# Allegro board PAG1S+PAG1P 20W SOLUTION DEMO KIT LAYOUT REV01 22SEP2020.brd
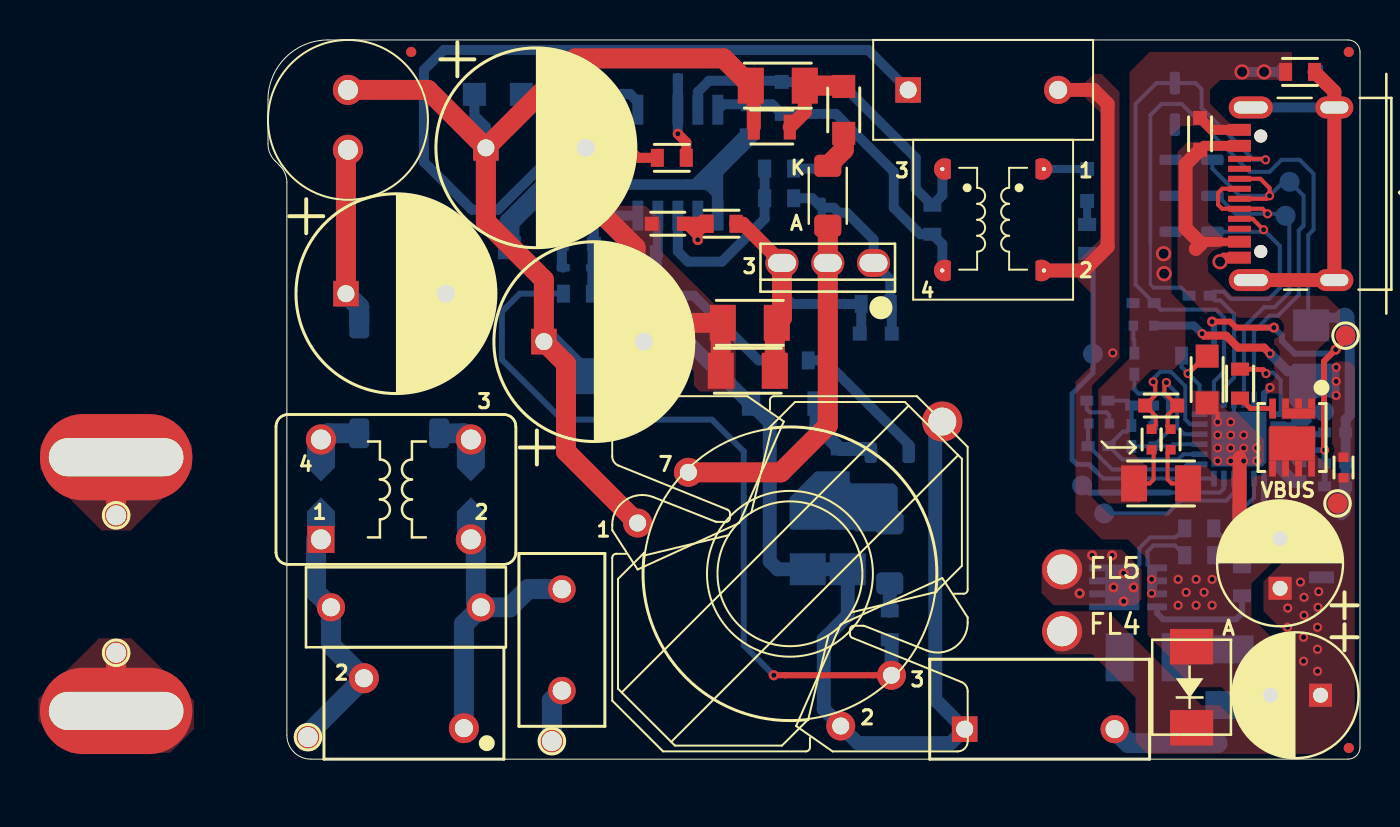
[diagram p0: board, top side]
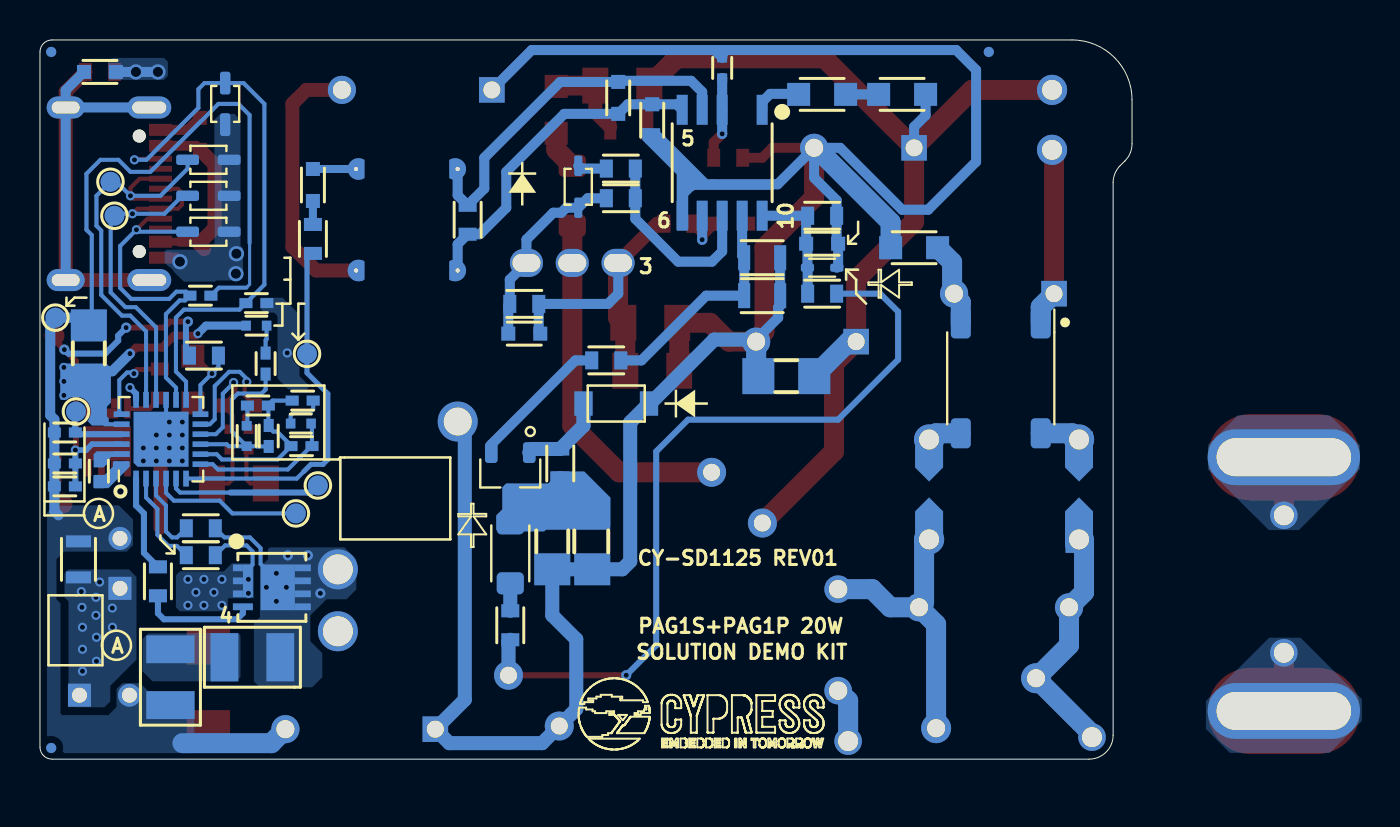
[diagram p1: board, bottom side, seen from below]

Outline 54.62 x 36 mm; copper layers: TOP, BOTTOM. Coordinates in mm from the lower left corner of the outline.
Outline path: 0,33 arc(0.88,35.12) 3,36 54.02,36 arc(54.45,35.82) 54.62,35.4 54.62,0.6 arc(54.45,0.18) 54.02,0 2.14,0 arc(1.3,0.35) 0.94,1.2 0.94,28.86 arc(0.85,29.32) 0.59,29.71 0.35,29.95 arc(0.09,30.34) 0,30.8 0,33

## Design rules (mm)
constraint set DEFAULT: min track width 0.152
net group 400V: nets N14642513 N14642535 VDC_IN
net group AC: nets L N N14611440 N14642330 N14642346
net group FET_DRAIN: nets N14787638 N14814894 N148149671
net group PRIMARY SIDE: nets N14785175 N14787619 N14791099 N14871077

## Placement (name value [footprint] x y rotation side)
ACC7  5200  [PCBBLADE]  -7.6 2.41 90 bottom
ACC8  5200  [PCBBLADE]  -7.6 15.11 90 bottom
BD1  ABS210-13  [SOPA4P400_505X640X170L100X60]  6.56 19.06 180 bottom
C1  10uF  [CAPPRD600W60D1000H2150]  6.4 23.3 0 top
C2  10uF  [CAPPRD600W60D1000H2150]  13.4 30.6 0 top
C3  10uF  [CAPPRD600W60D1000H2150]  16.3 20.9 0 top
C4  100pF  [CAPC1608X90N_TY]  30.4 21.3 180 bottom
C5  1nF  [CAPC2012X70N_MURATA]  25.2 31.64 0 top
C7  2.2nF  [1210]  44 5.1 0 bottom
C8  470uF  [CAPPRD250W50D630H1400]  50.62 9.8 90 top
C9  470uF  [CAPPRD250W50D630H1400]  51.4 3.2 180 top
C10  0.1uF  [CAPC1005X56N_CYPS]  51.68 14.41 270 bottom
C11  0.1uF  [CAPC1005X56N_CYPS]  53.38 13.65 0 bottom
C12  4.7uF  [CAPC1005X56N_CYPS]  53.38 14.8 0 bottom
C13  1uF  [CAPC1005X56N_CYPS]  53.38 16.35 0 bottom
C14  390pF  [CAPC1005X56N_CYPS]  46.6 23.2 180 bottom
C15  390pF  [CAPC1005X56N_CYPS]  43.8 22.83 180 bottom
C16  22nF  [SMD_1206]  17.29 19.17 0 bottom
C17  0.1uF  [CAPC1608X90N_TY]  24 31.98 270 bottom
C20  2.2uF  [SMD_1206]  29 10.9 270 bottom
C21  2.2uF  [SMD_1206]  27 10.9 270 bottom
C23  0.1uF  [CAPC1608X90N_TY]  44.68 17.7 180 top
C24  2.2uF  [CAPC1608X90N_TY]  46.62 31.3 90 top
C25  47nF  [CAPC1005X56N_CYPS]  41.48 17.95 0 bottom
C26  100pF  [CAPC1005X56N_CYPS]  41.54 15.67 0 bottom
C27  10pF  [CAPC1005X56N_CYPS]  43.18 16.18 90 bottom
C28  1nF  [CAPC1005X56N_CYPS]  43.72 17.7 180 bottom
C29  2.2nF  [CAPC1005X56N_CYPS]  43.34 19.8 270 bottom
C31  220pF  [CAPC1608X90N_TY]  20 26.8 180 top
C33  10pF  [CAPC1608X90N_TY]  15.5 25.8 180 bottom
C35  22uF  [CAPC2012X70N_MURATA]  18.5 25.1 180 bottom
C36  3.3nF  [CAPC1608X90N_TY]  40.97 28.74 270 bottom
C38  10uF  [SMD_1206]  52.18 20.31 90 bottom
C39  2200pF  [CAPC1608X90N_TY]  51.62 34.4 0 bottom
C40  10uF  [CAPC2012X70N_MURATA]  52.7 10 90 bottom
C41  22uF  [CAPC2012X70N_MURATA]  18.5 23.2 180 bottom
C42  10pF  [CAPC1608X90N_TY]  25.7 33.1 270 bottom
CX1  33nF, 310VAC  [BFC233820333]  6.9 7.6 180 top
CY1  220pF  [CAPRB750W60L1400T500H1600]  35.77 33.5 0 top
CY2  220pF  [CAPRB750W60L1400T500H1600]  38.6 1.5 0 top
D1  CGRKM4007-HF  [SODFL350X180X115L60X107N]  28 28.2 270 top
D3  RS1MSWF-7  [SODFL350X180X115L60X107N]  31.1 10.3 270 bottom
D5  BZT52C16-TP  [BZT52C12-TP_SOD123]  25.8 17.8 0 bottom
D7  1N4148WS  [SODFL250X125X90L60X30N]  27.7 28.65 270 bottom
D10  BAT54XV2T1G  [BAT54XV2T1G_SOD523]  15.5 24.6 180 bottom
D12  SMBJ5352B-TP  [DO214AA_MICRO]  46.2 3.6 270 top
D13  DESD5V0S1BA-7  [SOD250X130X110L30X30N]  46.2 26.4 180 bottom
D14  DESD5V0S1BA-7  [SOD250X130X110L30X30N]  45.36 32.8 270 bottom
D15  DESD5V0S1BA-7  [SOD250X130X110L30X30N]  46.2 28.2 180 bottom
D16  DESD5V0S1BA-7  [SOD250X130X110L30X30N]  46.2 30 180 bottom
DM  TEST_POINT  [TP-43R_S]  50.9 27.2 270 bottom
DP  TEST_POINT  [TP-43R_S]  51.1 28.9 90 bottom
F1  RSTA 2 AMMO  [FUSRR508W62L885T450H790]  14.7 5.97 270 top
GPIO0  TEST_POINT  [TP-43R_S]  40.72 13.7 90 bottom
GPIO1  TEST_POINT  [TP-43R_S]  41.27 20.29 180 bottom
J1  CU1816SAH1MD2R0-LF-HC  [USB-PD_TYPE-C]  55.94 28.3 90 top
L  TEST_POINT  [TP-43R_S]  14.2 0.9 0 top
L1  100uH, 0.5A  [INDRD300W60D800H10001]  4 32 90 top
L2  600ohm@100Mhz  [RESC2012X70N_PEC]  10.9 25.6 0 bottom
L_  TEST_POINT  [TP-43R_S]  -7.6 5.32 270 top
LF1  300uH, 1A  [L3]  6.4 13.5 0 top
N  TEST_POINT  [TP-43R_S]  2 1.1 0 top
N_  TEST_POINT  [TP-43R_S]  -7.6 12.2 270 top
NOREF  -  []  0.94 1.2 0 top
NOREF#2  -  []  0.08 30.36 0 top
NOREF#3  -  []  26.58 23.4 0 top
NOREF#4  -  []  -10.95 2.62 0 top
NOREF#5  -  []  -10.76 13.97 0 top
NOREF#6  -  [unnamed#2]  54.06 0.56 0 top
NOREF#7  -  []  -13.3 -0.84 0 top
NOREF#8  -  []  20.58 11.97 0 top
NOREF#9  -  []  123.79 -108.26 0 top
NOREF#10  -  []  36.82 30.44 0 top
NOREF#11  -  []  -13.6 17.78 0 top
NOREF#12  -  [unnamed#2]  54.06 35.4 0 top
NOREF#13  -  []  28.02 44.2 0 top
NOREF#14  -  []  40.6 5.64 0 top
NOREF#15  -  []  0 33 0 top
NOREF#16  -  []  54.46 0.19 0 top
NOREF#17  -  []  39.06 22.06 0 top
NOREF#18  -  []  123.79 -108.26 0 top
NOREF#19  -  []  1.62 35.66 0 top
NOREF#20  -  []  -12.85 -1 90 top
NOREF#21  -  [unnamed#2]  7.16 35.4 0 top
NOREF#22  -  []  38.6 8.7 0 top
NOREF#23  -  []  54.02 0 90 top
NOREF#24  -  [unnamed#2]  7.16 35.4 180 bottom
NOREF#25  -  [unnamed#2]  54.06 35.4 180 bottom
NOREF#26  -  [unnamed#2]  54.06 0.56 180 bottom
Q1  IPS70R900P7SAKMA1  [TO229P230X654X875-3B]  28 24.84 180 top
Q2  MMBTA06LT1G  [SOT23-3P95_240X100L40X44N]  31.1 14.3 0 bottom
Q3  BSZ097N10NS5ATMA1  [TSDSON65P330X330X110-8N_A]  43.02 8.6 180 bottom
Q4  BSZ0902NSATMA1  [TSDSON65P330X330X110-8N_A]  51.22 16.1 270 top
R1  820mohm  [RESC3216X65N_ROHM]  24 19.44 180 top
R2  47K  [RESC1608X55N_PEC]  30.4 22.79 0 bottom
R3  402K  [RESC3216X65N_ROHM]  25.5 33.72 0 top
R4  820mohm  [RESC3216X65N_ROHM]  24.1 21.84 180 top
R7  10E  [1210]  48.1 4.1 90 bottom
R8  5m  [RESC3216X65N_ROHM]  44.67 13.8 0 top
R11  100K  [RESC1608X55N_PEC]  46.42 20.2 0 bottom
R16  30E  [RESC1608X55N_PEC]  25.57 28.08 0 bottom
R17  3K  [RESC1608X55N_PEC]  33.23 27 270 bottom
R18  11E  [RESC1608X55N_PEC]  31.1 6.7 270 bottom
R19  1K  [RESC1608X55N_PEC]  22.68 26.8 0 top
R20  200K  [RESC1608X55N_PEC]  28.6 14.8 90 bottom
R21  49.9E  [RESC1608X55N_PEC]  40.97 26.04 90 bottom
R22  4.99K  [RESC1608X55N_PEC]  46.58 11.56 180 bottom
R23  0E  [RESC1005X40N_PEC]  45.15 16 270 top
R24  0E  [RESC1005X40N_PEC]  44.2 16 270 top
R25  2.2E  [RESC1608X55N_PEC]  48.72 8.9 270 bottom
R26  2.2E  [RESC1608X55N_PEC]  48.62 18.8 270 top
R27  40.2K  [RESC1005X40N_PEC]  41.57 16.8 180 bottom
R28  1.2M  [RESC1005X40N_PEC]  44.28 16.18 270 bottom
R29  1K  [RESC1005X40N_PEC]  43.8 21.7 0 bottom
R32  0E  [RESC1608X55N_PEC]  46.58 10.21 180 bottom
R36  499K  [RESC1608X55N_PEC]  20.2 30.1 0 top
R37  47 OHM  [RESC2012X70N_PEC]  15.5 33.27 180 bottom
R40  4.53K  [RESC1608X55N_PEC]  15.5 27.2 0 bottom
R41  0E  [RESC1608X55N_PEC]  51.62 34.4 180 top
R42  261K  [RESC1608X55N_PEC]  15.5 23.3 180 bottom
R43  47 OHM  [RESC2012X70N_PEC]  11.5 33.27 180 bottom
R44  100E  [RESC2012X70N_PEC]  28.8 32.5 90 top
R45  2.2E  [RESC1608X55N_PEC]  25.57 29.56 0 bottom
R48  0E  [RESC1608X55N_PEC]  26.3 19.96 0 bottom
R49  0E  [RESC1005X40N_PEC]  53.8 14.6 270 top
R50  499K  [RESC1005X40N_PEC]  20.5 34.6 270 bottom
RT1  100K  [RESC2012X70N_PEC]  46.98 19 90 top
SGND  TEST_POINT  [TP-43R_S]  53.85 22.1 90 bottom
T1  -  [RM7]  26.11 9.28 0 top
T2  1:3  [RADIAL_R113426000]  36.27 27 180 top
U1  PAG1S  [QFN50P400X400X60-25T275X275N]  48.57 16.01 90 bottom
U2  PAG1P  [SOIC100P600X175-10N_CYPS]  20.5 29.85 270 bottom
VBUS_IN  TEST_POINT  [TP-43R_S]  53.5 12.8 90 top
VCCD  TEST_POINT  [TP-43R_S]  52.82 17.4 180 bottom
VDDD  TEST_POINT  [TP-43R_S]  53.9 21.2 0 top
VR1  V320LA7P  [VAR_V320LA7P]  7.3 2.8 180 top
XRES  TEST_POINT  [TP-43R_S]  41.82 12.3 270 bottom

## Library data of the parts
ACC7 ACC8 = HEYCO PCB BLADE 5201_0
BD1 = BR805D_1
C1-C3 C8 C9 = CAP_2
C4 C5 C7 C10-C17 C20 C21 C23-C29 C31 C33 C35 C36 C38-C42 CX1 CY1 CY2 = 0_0.01uF-50V-10%-X7R-0603
D1 D7 = DIODE_13
D3 = DIODE_17
D5 D12 = DIODE SCHOTTKY_19
D10 = DIODE SCHOTTKY_21
D13-D16 = TVS DIODE_1
DM DP GPIO0 GPIO1 L L_ N N_ SGND VBUS_IN VCCD VDDD XRES = TEST_POINT
F1 = Fuse 2
J1 = USB-PD_TYPE-C_7
L1 L2 = INDUCTOR_PAG1S_1
LF1 = INDUCTOR IRON_8
Q1 = IPP65R380E6XKSA1_1
Q2 = 2N1070_1
Q3 Q4 = DMTH10H010LCT_5
R1-R4 R7 R8 R18 R20 = RESISTOR
R11 R16 R17 R19 R21-R29 R32 R36 R37 R40-R45 R48-R50 = 330 ohm 5% 0805_0
RT1 = RESISTOR VAR 2_4
T1 = PA5222NL_35
T2 = TRANSFORMER_11
U1 = PAG1S_11
U2 = PAG1P_3
VR1 = RESISTOR VAR 2_0

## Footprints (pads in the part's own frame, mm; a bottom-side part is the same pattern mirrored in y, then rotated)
1210
  rect 1.397x2.413 smd: 1(-1.397,0) 2(1.397,0)
BAT54XV2T1G_SOD523
  custom 0.1x0.1 smd: A(0.735,0) C(-0.735,0)
BFC233820333
  round 1.412 hole 0.904: 1(-3.75,0) 2(3.75,0)
BZT52C12-TP_SOD123
  rect 0.914x1.219 smd: A(-1.638,0) K(1.638,0)
CAPC1005X56N_CYPS
  rect 0.65x0.5 smd: 1(-0.525,0) 2(0.525,0)
CAPC1608X90N_TY
  rect 0.7x0.7 smd: 1(-0.8,0) 2(0.8,0)
CAPC2012X70N_MURATA
  rect 0.6x1.25 smd: 1(-0.9,0) 2(0.9,0)
CAPPRD250W50D630H1400
  rect 1.15x1.15 hole 0.75: 1(-1.25,0)
  round 1.15 hole 0.75: 2(1.25,0)
CAPPRD600W60D1000H2150
  rect 1.28x1.28 hole 0.85: 1(-2.5,0)
  round 1.412 hole 0.904: 2(2.5,0)
CAPRB750W60L1400T500H1600
  rect 1.28x1.28 hole 0.85: 1(-3.75,0)
  round 1.412 hole 0.904: 2(3.75,0)
DO214AA_MICRO
  rect 1.778x2.159 smd: A(-2.032,0) K(2.032,0)
FUSRR508W62L885T450H790
  round 1.38 hole 0.92: 1(-2.54,0) 2(2.54,0)
INDRD300W60D800H10001
  round 1.508 hole 1: 1(-1.5,0) 2(1.5,0)
L3
  rect 1.35x1.35 hole 1: 1(-3.75,-2.5)
  round 1.508 hole 1: 2(3.75,-2.5) 3(3.75,2.5) 4(-3.75,2.5)
PCBBLADE
  oval 4.318x7.62 hole 1.905x6.731: 1(0,0)
QFN50P400X400X60-25T275X275N
  rect 0.79x0.28 smd: 1(-1.97,1.25) 2(-1.97,0.75) 3(-1.97,0.25) 4(-1.97,-0.25) 5(-1.97,-0.75) 6(-1.97,-1.25) 13(1.97,-1.25) 14(1.97,-0.75) 15(1.97,-0.25) 16(1.97,0.25) 17(1.97,0.75) 18(1.97,1.25)
  rect 0.28x0.79 smd: 7(-1.25,-1.97) 8(-0.75,-1.97) 9(-0.25,-1.97) 10(0.25,-1.97) 11(0.75,-1.97) 12(1.25,-1.97) 19(1.25,1.97) 20(0.75,1.97) 21(0.25,1.97) 22(-0.25,1.97) 23(-0.75,1.97) 24(-1.25,1.97)
  custom 0.687x0.687 smd: 25(0,0)
RADIAL_R113426000
  custom 0.21x0.21 hole 0.7: 1(-2.54,-2.54) 2(-2.54,2.54) 3(2.54,-2.54) 4(2.54,2.54)
RESC1005X40N_PEC
  rect 0.475x0.5 smd: 1(-0.512,0) 2(0.512,0)
RESC1608X55N_PEC
  rect 0.65x0.9 smd: 1(-0.725,0) 2(0.725,0)
RESC2012X70N_PEC
  rect 1.15x1.15 smd: 1(-1.175,0) 2(1.175,0)
RESC3216X65N_ROHM
  rect 1.3x1.8 smd: 1(-1.35,0) 2(1.35,0)
RM7
  round 1.45 hole 0.85: 1(-7.62,2.54) 2(2.54,-7.62) 3(5.08,-5.08) 7(-5.08,5.08)
  round 2 hole 1.5: 9(13.615,0.222) 10(13.615,-2.878)
  round 2 hole 1.4: 11(7.62,7.62)
SMD_1206
  rect 1.6x1.803 smd: 1(-1.397,0) 2(1.397,0)
SOD250X130X110L30X30N
  custom 0.13x0.13 smd: A(1.04,0) C(-1.04,0)
SODFL250X125X90L60X30N
  custom 0.1x0.1 smd: A(1.05,0) C(-1.05,0)
SODFL350X180X115L60X107N
  custom 0.278x0.278 smd: A(1.5,0) C(-1.5,0)
SOIC100P600X175-10N_CYPS
  rect 1.5x0.55 smd: 1(-2.65,2) 3(-2.65,0) 4(-2.65,-1) 5(-2.65,-2) 6(2.65,-2) 7(2.65,-1) 8(2.65,0) 9(2.65,1) 10(2.65,2)
SOPA4P400_505X640X170L100X60
  custom 0.25x0.25 smd: 1(2,2.75) 2(2,-2.75) 3(-2,2.75) 4(-2,-2.75)
SOT23-3P95_240X100L40X44N
  custom 0.158x0.158 smd: 1(-0.95,-1.045) 2(0.95,-1.045) 3(0,1.045)
TO229P230X654X875-3B
  oval 1.654x1.408 hole 1.4x0.9: 1(-2.29,0) 2(0,0) 3(2.29,0)
TP-43R_S
  round 1.38 hole 1: 1(0,0)
TSDSON65P330X330X110-8N_A
  rect 0.5x0.34 smd: 1(-1.7,0.975) 2(-1.7,0.325) 3(-1.7,-0.325)
  rect 1x0.34 smd: 4(-1.45,-0.975)
  rect 0.8x0.34 smd: 5(1.55,-0.975) 6(1.55,-0.325) 7(1.55,0.325) 8(1.55,0.975)
unnamed#2
  round 0.508 smd: (0,0)
USB-PD_TYPE-C
  round 0.65 hole 0.65 unplated: (-2.89,6.28) (2.89,6.28)
  rect 0.6x1.15 smd: A1(-3.2,7.345) A4(-2.4,7.345) B1(3.2,7.345) B4(2.4,7.345)
  rect 0.3x1.15 smd: A5(-1.25,7.345) A6(-0.25,7.345) A7(0.25,7.345) A8(1.25,7.345) A9(2.4,7.345) A12(3.2,7.345) B5(1.75,7.345) B6(0.75,7.345) B7(-0.75,7.345) B8(-1.75,7.345) B9(-2.4,7.345) B12(-3.2,7.345)
  oval 1.1x1.9 hole 0.6x1.4: MH1(-4.32,2.6) MH2(4.32,2.6)
  oval 1.1x2.2 hole 0.6x1.7: MH3(4.32,6.78) MH4(-4.32,6.78)
VAR_V320LA7P
  round 1.5 hole 0.904: 1(-2.5,1.25) 2(2.5,-1.25)

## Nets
VBUS_C: C24.1 J1.A4 J1.A9 J1.B4 J1.B9(VBUS_4) Q4.1 Q4.2 Q4.3(S#3) U1.18
VBUS_IN: C8.1 C9.1 C40.1 D12.K Q4.5 Q4.6 Q4.7 Q4.8 R49.2 T1.10 VBUS_IN.1
VCCD: C13.1 U1.21 VCCD.1
VDDD: C11.1 C12.1 R11.2 U1.22 VDDD.1
CC1: C14.1 D13.C J1.A5 U1.14
CC2: C15.1 D14.C J1.B5 U1.13
DM_GPIO4: D15.C DM.1 J1.A7 J1.B7 U1.16
DP_GPIO5: D16.C DP.1 J1.A6 J1.B6 U1.17
L: F1.2 L.1
L_: ACC7.1 L_.1
N: CX1.2 LF1.1 N.1 VR1.2
N_: ACC8.1 N_.1
PE_GND: C2.2 C3.2 C16.2 C17.2 C20.2 C21.2 C31.2 C33.2 C35.2 C41.2 CY1.1 CY2.1 D5.A D10.A L2.2 R1.2 R4.2 R36.1 R40.1 R50.1 T1.2 T1.11 U2.6
PWM_DRV_GPIO1: GPIO1.1 R21.1 U1.6
SE_GND: C8.2 C9.2 C11.2 C12.2 C13.2 C14.2 C15.2 C38.2 C40.2 CY1.2 CY2.2 D12.A Q3.1 Q3.2 Q3.3(S#3) R7.1 R8.2 R23.2 R32.2 RT1.1 SGND.1 T2.2 U1.15 U1.25
SR_GDRV: R25.1 U1.1
SR_SENSE: R22.1 U1.3
TYPE-C_GND: C24.2 C39.1 D13.A D14.A D15.A D16.A J1.A1 J1.A12 J1.B1 J1.B12 R8.1 R24.2 R41.2
VDC_IN: C2.1 C3.1 C5.1 C16.1 L1.2 R3.1 R43.2 T1.1
N14611440: CX1.1 F1.1 LF1.2 VR1.1
N14642330: BD1.4 LF1.3
N14642346: BD1.2 LF1.4
N14642513: BD1.1(DC OUT PLUS) C1.1 L1.1
N14642535: BD1.3 C1.2 L2.1
N14649078: C7.1 Q3.5 Q3.6 Q3.7 Q3.8 R22.2 T1.9(OUT3)
N14679612: Q4.4 R26.2
N14684319: R11.1 RT1.2 U1.12
N14693071: C23.1 R23.1 U1.10
N14693222: C23.2 R24.1 U1.11
N14693774: GPIO0.1 U1.5
N14694144: C25.2 C26.2 C27.2 C28.2 U1.8
N14694182: C26.1 R27.2 U1.7
N14694200: C27.1 C29.2 R28.2 U1.9
N14702573: C38.1 R29.2 R49.1 U1.20
N14702669: C10.2 U1.24
N14702673: C10.1 U1.23
N14714455: U1.4(XRES) XRES.1
N14737770: R32.1 U1.2
N14785175: D5.K Q2.1 R20.2
N14785189: C20.1 C21.1 D3.C Q2.3 R20.1
N14787619: Q2.2(E) R48.2
N14787638: D1.A Q1.2 T1.7
N14791099: C35.1 C41.1 R48.1 U2.9
N14814894: C5.2 R3.2 R44.2
N14820915: C39.2 J1.MH1 J1.MH2 J1.MH3 J1.MH4 R41.1
N14862097: C4.1 D7.A Q1.1 R2.2 R16.2
N14862239: R16.1 R45.1 U2.8
N14862483: C17.1 C42.2 R17.2 T2.4 U2.5
N14862590: C42.1 R17.1 T2.3 U2.4
N14862769: C31.1 R19.1 U2.7
N14862985: R37.1 U2.1(VDD700)
N14865019: C33.1 D10.C(K) R40.2 R42.1 U2.10
N14871077: C4.2 Q1.3(S) R1.1 R2.1 R4.1 R19.2
N14908282: R36.2 R50.2 U2.3
N14923159: R37.2 R43.1
N14933197: R26.1 U1.19
N14933813: D3.A R18.1
N14956400: D7.C R45.2
N14974360: C36.2 R21.2
N14974376: C36.1 T2.1
N14975051: C28.1 R28.1
N14975285: C25.1 R27.1
N14978138: Q3.4 R25.2
N14987684: R18.2 R42.2 T1.3
N148149671: D1.C R44.1
N149872480: C29.1 R29.1
N158920421: C7.2 R7.2

Pads without a net: J1 A8 B8

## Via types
v1: diameter 0.457, hole 0.254, TOP to BOTTOM, 51 vias
v2: diameter 0.508, hole 0.254, TOP to BOTTOM, 13 vias
v3: diameter 0.762, hole 0.508, TOP to BOTTOM, 5 vias

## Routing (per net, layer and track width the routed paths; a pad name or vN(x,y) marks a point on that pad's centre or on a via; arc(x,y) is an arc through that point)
VBUS_C: length 10.5
  TOP w0.4: 47.62,25.9 J1.A4
  TOP w0.5: C24.1 46.82,30.7 J1.A9 ; 46.67,25.8 46.77,25.9 47.62,25.9
  TOP w0.7: 46.41,25.54 46.67,25.8 45.9,26.57 45.9,29.78 C24.1
  BOTTOM w0.3: U1.18 49.82,18.29 v1(50.12,18.6)
VBUS_IN:
  vias: v1(51.01,7.56) v1(51,6.6) v1(51.64,8.86) v1(51.82,8.1) v1(51.82,7.2) v1(51.8,6.1) v1(51.8,4.9) v1(52.52,7.6) v1(52.5,6.6) v1(52.5,5.5) v1(52.5,4.4) v1(52.56,8.39)
VCCD: length 3.4
  BOTTOM w0.3: U1.21 52.77,16.26 C13.1 52.88,16.38 52.88,17.34 VCCD.1
VDDD: length 19.3
  TOP w0.3: VDDD.1 53.9,20.99 v2(53.41,20.5) 52.82,19.92 52.82,15.5 v1(52.85,15.47) ; v2(50.31,21.6) 48.42,21.6 48.12,21.9 v2(47.22,21.9)
  BOTTOM w0.28: U1.22 52.02,15.76 52.32,15.47 v1(52.85,15.47)
  BOTTOM w0.3: v2(50.31,21.6) 50.71,21.2 50.71,20.95 51.36,20.3 53.21,20.3 v2(53.41,20.5) ; R11.2 47.32,20.38 47.32,21.8 v2(47.22,21.9) ; C11.1 C12.1 v1(52.85,15.47)
CC1: length 17.3
  TOP w0.203: v1(49.8,26.5) 49.25,27.05 J1.A5
  BOTTOM w0.203: U1.14 47.82,18.59 48.32,19.1 48.32,22.28 47.64,22.96 47.36,22.96 C14.1 47.32,23.4 47.8,23.4 48.16,23.04 50.06,23.04 50.62,23.59 50.62,25.68 v1(49.8,26.5) 49.7,26.4 D13.C
CC2: length 28.9
  TOP w0.203: v1(49.9,30) 49.85,30.05 J1.B5
  BOTTOM w0.203: v1(49.9,30) 49.3,30 46.7,32.6 46.7,33.54 46.4,33.84 D14.C 44.44,33.84 43.4,32.8 43.4,23.75 C15.1 44.65,22.5 47.42,22.5 47.82,22.1 47.82,19.4 47.32,18.89 U1.13
DM_GPIO4: length 19
  TOP w0.203: J1.A7 47.73,28.55 47.52,28.35 47.52,27.75 47.73,27.55 J1.B7 49.75,27.55 v1(50,27.3)
  BOTTOM w0.203: D15.C 47.5,28.2 48.4,27.3 v1(50,27.3) 50.8,27.3 DM.1 51.09,27.01 51.09,23.36 50.35,22.62 49.83,22.62 48.82,21.61 U1.16
DP_GPIO5: length 21.3
  TOP w0.203: J1.B6 49.64,29.05 50.1,28.59 v1(50.1,28.2) 49.95,28.05 J1.A6
  BOTTOM w0.203: U1.17 49.32,21.41 50.11,22.2 50.52,22.2 51.56,23.24 51.56,26.46 51.8,26.7 51.8,28.2 DP.1 50.8,28.9 v1(50.1,28.2) 48.6,28.2 47.24,29.56 D16.C
L: length 2.7
  BOTTOM w1: L.1 14.2,2.93 14.7,3.43
L_: length 2.9
  TOP w1: ACC7.1 L_.1
N: length 12.1
  BOTTOM w1: 2.4,11 2.4,8.35 CX1.2 3.15,5.7 VR1.2 2,1.25 N.1
N_: length 2.9
  TOP w1: ACC8.1 N_.1
PE_GND: length 145.5
  TOP w0.5: R36.1 18.5,30.1 18,30.6 C2.2
  TOP w1: C2.2 15.9,28.1 18.39,25.61 18.39,21.41 18.8,21 C3.2 20.17,20.9 21.11,21.84 R4.2 22.65,21.74 R1.2
  BOTTOM w0.5: 20.3,35.49 20.5,35.3 R50.1 20.88,35.49 ; 20.3,35.49 8.79,35.49 7.8,34.5 7.8,29.9 10.2,27.5 11.5,27.5 14.6,30.6 15.8,30.6 ; 20.3,35.49 20.88,35.49 ; 22,28.7 21.93,28.77 ; 21.93,28.77 22.43,28.77 22.43,29.33 23.82,30.72 ; 21.93,28.77 17.72,28.77 C2.2 15.9,29.1 14.78,27.98 R40.1 14.78,25.88 C33.2 14.7,24.66 D10.A ; 20.88,35.49 30.03,35.49 CY1.1 ; C35.2 C41.2 17.6,22.7 17.7,22.6 17.7,22.1 18.8,21 C3.2 ; U2.6 22.5,28.7 ; 23.47,30.45 24.1,31.08
  BOTTOM w0.7: T1.11 33.37,16.54 33.37,2.98 CY2.1 34.15,0.8 29.51,0.8 T1.2 27.8,2.51 27.8,6 29,7.2 C20.2 C21.2 25.5,9.5 25.1,9.9 25.1,16.86 D5.A 24.1,17.8 20.9,21 18.9,21 C3.2
  BOTTOM w1: C2.2 15.8,30.6 12.08,26.88 L2.2 ; C3.2 18.8,19.28 C16.2
PWM_DRV_GPIO1: length 18.4
  BOTTOM w0.203: U1.6 41.78,14.04 41.42,14.4
  BOTTOM w0.25: 41.42,14.4 41.07,14.76 40.47,14.76 40.22,15 40.22,18.29 41.27,19.33 GPIO1.1 41.27,25.02 40.97,25.32
SE_GND: length 72.2
  TOP w0.203: RT1.1 47.51,17.3 v1(47.51,16.87) ; R23.2 45,15.34 45,14 45.2,13.8 R8.2
  TOP w0.7: CY1.2 41.3,33.5 42,32.8 42,25.65 40.81,24.46 T2.2 ; 48.6,15.1 48.6,11.6
  BOTTOM w0.152: 44.3,23.6 44.14,23.76 44.14,25.84
  BOTTOM w0.2: R32.2 45.37,10.7 44.29,10.7 43.99,10.4 43.99,9.73 44.12,9.6
  BOTTOM w0.203: C38.2 52.03,21.86 52.03,26.23 52.3,26.5 52.3,29.3 51.6,30 50.7,30 50.1,29.4 49.1,29.4 45.7,32.8 44.7,32.8 44.14,32.24 44.14,25.84 ; U1.25 48.32,16.26 U1.15 ; 44.3,23.6 45.67,23.6 C14.2
  BOTTOM w0.5: 53.7,12.2 53.9,12.4 C11.2 C12.2 C13.2 53.9,17 54.11,17.21 54.11,21.84 SGND.1 52.57,22.1 C38.2
  BOTTOM w1: 47.5,0.8 43.05,0.8 CY2.2
  vias: v1(42.26,20.33) v1(44.2,9) v1(44.2,8.3) v1(45.52,9) v1(45.52,7.7) v1(45.92,8.35) v1(46.42,9) v1(46.42,7.7) v1(46.82,8.35) v1(47.22,9) v1(47.22,7.7) v1(47.51,16.22) v1(47.51,15.57) v1(47.51,14.92) v1(48.16,16.87) v1(48.16,16.22) v1(48.16,15.57) v1(48.16,14.92) v1(48.81,16.22) v1(48.81,15.57) v1(48.81,14.92) v1(49.46,15.57) v1(49.46,14.92)
SR_GDRV: length 4.9
  BOTTOM w0.3: U1.1 49.82,12.69 49.42,12.3 49.42,10.32 R25.1
SR_SENSE: length 4.2
  BOTTOM w0.2: R22.1 47.76,11.1 48.02,11.1 48.32,11.4 48.32,12.7 48.82,13.19 U1.3
TYPE-C_GND: length 8
  TOP w0.203: R8.1 44.1,13.8 44.3,14 44.3,15.39 R24.2
  TOP w0.5: v3(47.62,24.9) 47.82,25.1 J1.A1 ; C24.2 47.22,31.5 J1.A12
  BOTTOM w0.5: v3(48.72,34.4) v3(49.82,34.4) C39.1
  vias: v3(44.8,25.3) v3(44.82,24.3)
VDC_IN: length 53.6
  TOP w0.7: C5.1 24.3,33.56 R3.1
  TOP w1: T1.1 14.91,15.4 14.91,19.79 C3.1 13.8,24 10.9,26.9 C2.1 ; C2.1 8,33.5 L1.2 ; C2.1 15.38,35.08 22.79,35.08 R3.1
  BOTTOM w0.5: R43.2 10.33,32.23 10.9,31.65 C2.1
  BOTTOM w1: C16.1 14.17,20.9 C3.1
N14611440: length 14.3
  BOTTOM w1: 10.4,11 10.4,7.85 CX1.1 ; CX1.1 9.8,6.75 VR1.1 ; CX1.1 12.09,7.6 13,8.51 F1.1
N14642330: length 2
  BOTTOM w1: 10.4,16 LF1.3 10.12,16 9.81,16.31 BD1.4
N14642346: length 2.3
  BOTTOM w1: 2.4,16 LF1.4 2.68,16 2.99,16.31 BD1.2
N14642513: length 9
  TOP w1: C1.1 3.9,30.4 L1.1
  BOTTOM w1: BD1.1 4.56,22.64 C1.1
N14642535: length 4.3
  BOTTOM w1: BD1.3 8.56,22.86 8.9,23.2 C1.2 9,23.4 9,24.88 L2.1
N14649078: length 3.7
  BOTTOM w0.2: 43.42,9.6 43.59,9.76 43.59,10.56 44.12,11.1 45.4,11.1 R22.2
  vias: v2(40.6,8.3) v2(41.22,10.2) v2(42.22,10.2) v2(42.3,8.6) v2(42.8,9.3) v2(42.8,7.9) v2(43.3,8.6)
N14679612: length 1.8
  TOP w0.25: R26.2 49.15,17.55 Q4.4
N14684319: length 4.6
  TOP w0.25: RT1.2 46.9,20.18 v1(46.02,19.3)
  BOTTOM w0.2: v1(46.02,19.3) 46.6,18.73 U1.12
  BOTTOM w0.203: R11.1 45.7,19.62 v1(46.02,19.3)
N14693071: length 6.6
  TOP w0.203: R23.1 45,16.66 45,17.22 C23.1 44.84,18.33 44.84,18.76 v1(44.94,18.85)
  BOTTOM w0.2: v1(44.94,18.85) 44.94,18.83 45.48,18.29 45.48,16.61 45.83,16.26 U1.10
N14693222: length 7.6
  TOP w0.203: v1(44.28,18.88) 44.38,18.78 44.38,18.21 C23.2 44.4,17.18 44.4,16.71 R24.1
  BOTTOM w0.2: v1(44.28,18.88) 44.28,19.04 44.63,19.39 45.17,19.39 45.88,18.67 45.88,17.01 46.13,16.76 U1.11
N14693774: length 7.8
  BOTTOM w0.203: 45.09,13.34 47.62,13.34 47.82,13.55 U1.5
  BOTTOM w0.3: 45.09,13.34 41.08,13.34 GPIO0.1
N14694144: length 8.8
  BOTTOM w0.203: C25.2 43,17.95 43.2,17.74 C28.2 43.2,16.72 C27.2 43.18,16.63 42.96,16.4 42.77,16.4 42.14,15.78 42.14,15.74 C26.2 42.74,15 45.52,15 45.79,15.26 U1.8
N14694182: length 7.3
  BOTTOM w0.203: U1.7 45.99,14.76 45.72,14.5 42.22,14.5 41.06,15.67 C26.1 41.02,16.76 R27.2
N14694200: length 8.8
  BOTTOM w0.203: U1.9 45.29,15.76 45.19,15.66 R28.2 ; R28.2 43.78,15.66 43.77,15.65 C27.1 ; R28.2 45.02,16.4 45.02,18 44.72,18.3 43.54,18.3 43.34,18.5 C29.2
N14702573: length 10.7
  TOP w0.4: v1(50.12,20.3) 49.82,20.6 48.52,20.6 47.92,21.2 46.82,21.2 v1(46.72,21.3)
  BOTTOM w0.2: 51.9,17.3 51.36,16.76 U1.20
  BOTTOM w0.4: v1(46.72,21.3) 46.32,21.7 R29.2
  BOTTOM w0.5: C38.1 51.88,19.22 51.41,19.22 51.41,19.42 51.01,19.42 v1(50.12,20.3)
  vias: v1(53.43,19.61) v1(53.43,18.91) v1(53.43,18.21)
N14714455: length 7.6
  BOTTOM w0.203: XRES.1 45,12.3 45.64,12.94 47.93,12.94 48.32,13.33 U1.4
N14737770: length 4.9
  BOTTOM w0.2: U1.2 49.32,13.09 49.12,12.89 48.75,12.52 48.75,11.22 48.2,10.68 47.77,10.68 R32.1
N14785175: length 4.4
  BOTTOM w0.7: D5.K 27.44,16.69 R20.2 29.97,15.53 Q2.1
N14785189: length 7.7
  BOTTOM w0.7: R20.1 28.6,12.7 C20.1 ; Q2.3 D3.C 29.5,11.8 C20.1 ; C20.1 C21.1
N14787619: length 7.2
  BOTTOM w0.5: Q2.2 32.05,15.75 27.84,19.96 R48.2
N14787638: length 17.9
  TOP w1: D1.A Q1.2 28,16.7 25.66,14.36 T1.7
N14791099: length 11.6
  BOTTOM w0.5: 25.57,19.96 24.54,19.96 21.3,23.2 C41.1 C35.1 19.5,25.2 U2.9
N14814894: length 4.4
  TOP w0.7: C5.2 26.85,32.39 R3.2
  TOP w1: R44.2 28.76,33.72 R3.2
N14820915: length 30
  TOP w0.7: R41.1 53.34,33.41 J1.MH2 J1.MH1 J1.MH4
  BOTTOM w0.5: J1.MH2 53.34,33.48 C39.2 ; J1.MH2 J1.MH3 ; J1.MH2 J1.MH1
N14862097: length 9.9
  BOTTOM w0.5: C4.1 31.2,22.71 R2.2 31.12,24 Q1.1 30.29,26.01 28.95,27.35 28.55,27.35 28.3,27.6 D7.A 27.22,28.08 R16.2
N14862239: length 9.7
  BOTTOM w0.5: U2.8 20.5,25.41 21.01,24.9 22.7,24.9 24.84,27.05 R16.1 R45.1
N14862483: length 16.6
  BOTTOM w0.5: T2.4 33.73,25.77 R17.2 32.62,26.27 31.3,27.6 31.3,29.4 28.4,32.3 C42.2 25.22,32.78 C17.1 22.78,32.78 U2.5
N14862590: length 18.4
  BOTTOM w0.5: T2.3 33.73,28.23 R17.1 32.4,28.56 32.4,30.1 28.6,33.9 C42.1 25.65,33.95 22.06,33.95 21.5,33.4 U2.4
N14862769: length 1.2
  BOTTOM w0.5: U2.7 v2(21.5,26)
N14862985: length 2.4
  BOTTOM w0.5: U2.1 18.5,32.9 18.1,33.3 16.77,33.3 16.75,33.27 R37.1
N14865019: length 6.2
  BOTTOM w0.5: U2.10 18.5,27.2 R40.2 16.3,27.12 C33.1 16.23,25.73 16.23,24.6 16.22,24.59 R42.1
N14871077: length 15.9
  TOP w0.7: Q1.3 23.75,26.8 R19.2
  TOP w1: R1.1 25.35,21.74 R4.1 25.71,22.1 Q1.3
  BOTTOM w0.5: C4.2 29.67,21.38 R2.1 26.21,22.79 25.7,23.3 25.7,24.83 Q1.3
N14908282: length 4.2
  TOP w0.5: v2(20.5,31.3) 20.92,30.88 20.92,30.1
  BOTTOM w0.5: v2(20.5,31.3) U2.3 20.5,34.09 R50.2
N14923159: length 1.7
  BOTTOM w0.5: R37.2 R43.1
N14933197: length 4.1
  TOP w0.25: v1(49.92,19.3) 49.92,19.35 49.78,19.5 49.41,19.5 49.39,19.52 48.62,19.52
  BOTTOM w0.2: U1.19 50.66,17.38 50.66,18.97 50.27,19.35 49.98,19.35 v1(49.92,19.3)
N14933813: length 1.4
  BOTTOM w0.7: R18.1 D3.A
N14956400: length 1.5
  BOTTOM w0.5: D7.C 27.56,29.56 R45.2
N14974360: length 1.2
  BOTTOM w0.4: R21.2 C36.2
N14974376: length 2.2
  BOTTOM w0.4: C36.1 T2.1
N14975051: length 1
  BOTTOM w0.203: R28.1 44.25,16.72 C28.1
N14975285: length 2.1
  BOTTOM w0.203: R27.1 42.09,17.21 41.93,17.36 41.11,17.36 40.96,17.52 C25.1
N14978138: length 5.7
  BOTTOM w0.3: Q3.4 44.47,7.3 44.77,7 48.42,7 48.72,7.3 R25.2
N14987684: length 39.4
  TOP w0.3: T1.3 25.87,4.2 25.86,4.2 v2(25.3,4.2)
  BOTTOM w0.3: v2(25.3,4.2) 23.8,5.7 23.8,15.4 22.21,16.99 14.71,16.99 11.7,20 11.7,22.4 12.6,23.3 R42.2
  BOTTOM w0.7: T1.3 31.19,5.89 R18.2
N148149671: length 2
  TOP w1: R44.1 28.8,30.5 D1.C
N149872480: length 1.4
  BOTTOM w0.203: C29.1 43.34,20.97 43.29,21.02 R29.1

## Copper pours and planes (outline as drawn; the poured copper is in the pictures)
VBUS_C on TOP: 52.42,17 52.42,20.4 53.62,21.6 53.62,22.5 52.92,23.2 48.22,23.2 47.02,24.4 47.02,25 47.62,25.59 48.51,25.59 48.68,25.76 48.68,25.96 48.53,26.11 47.79,26.11 47.02,26.88 47.02,30.6 46.72,30.9 46,30.9 45.5,30.4 45.5,23.7 46.9,22.3 48.32,22.3 48.52,22.1 50.52,22.1 50.72,21.9 50.72,21.4 50.32,21 50.32,19.4 49.92,19 49.9,19 49.9,18.3 50.6,18.3 50.7,18.2 50.7,17
VBUS_IN on TOP (solid shape): 52.37,14.95 50.08,14.95 50.08,16.66 52.37,16.66
VBUS_IN on TOP: 49.8,8.9 49.8,7.4 51.4,5.8 51.4,2.6 50.8,2 48.3,2 47.6,2.7 46.7,2.7 42,7.4 39.4,7.4 38.8,6.8 38.8,5.92 39.47,5.25 41.23,5.25 43.4,3.08 43.4,0.86 44,0.26 52.78,0.26 54.37,1.84 54.37,14.3 53.4,14.3 52.6,15.1 52.6,15.12 52.52,15.2 52.52,16.48 52.3,16.7 50.2,16.7 50.02,16.52 50.02,14.5 49.72,14.2 49.42,14.2 49.22,14 49.22,12.7 49.52,12.4 51.2,12.4 51.8,11.8 51.8,10.9
VBUS_IN on BOTTOM: 49.8,9.13 49.8,4.97 51.1,3.67 51.1,2.9 51.4,2.6 52.9,2.6 53.2,2.9 53.2,7.9 53.4,8.1 53.4,9.3 53.2,9.5 50.17,9.5
(no net) on BOTTOM: 51.08,19.58 51.08,17.84 51.28,17.64 51.28,17.16 51.12,17 51.12,16.8 51.22,16.7 52.02,16.7 52.25,16.92 52.25,17.08 52.28,17.11 52.28,17.76 52.52,18 53.66,18 53.66,19.66 53.52,19.8 51.3,19.8
L_ on TOP: -4.9,0.31 -9.9,0.31 -11.5,1.91 -11.5,3.01 -8.46,6.05 -6.84,6.05 -3.7,2.91 -3.7,1.51
L_ on BOTTOM: -4.9,0.31 -9.9,0.31 -11.5,1.91 -11.5,3.01 -8.44,6.07 -6.86,6.07 -3.7,2.91 -3.7,1.51
N on BOTTOM (solid shape): 3.35,12.4 3.35,10.6 2.05,10.6 1.95,10.7 1.95,12.4 2.65,13.1
N_ on TOP: -3.8,15.71 -3.8,14.51 -6.87,11.44 -8.33,11.44 -11.4,14.51 -11.4,15.71 -9.9,17.21 -5.3,17.21
N_ on BOTTOM: -3.8,15.71 -3.8,14.51 -6.85,11.46 -8.35,11.46 -11.4,14.51 -11.4,15.71 -9.9,17.21 -5.3,17.21
PE_GND on BOTTOM (solid shape): 24.5,31 22.77,29.27 22.77,26.5 22.2,26.5 22.2,28.2 21.9,28.5 17.9,28.5 17.9,29 21.2,29 23.6,31.4 23.6,31.56 23.63,31.58 24.5,31.58
PE_GND on TOP: 17.8,20.7 18.5,20 20.7,20 21.3,19.4 21.3,18.7 21.6,18.4 23.2,18.4 23.4,18.6 23.4,22.5 23.15,22.75 22.35,22.75 19.65,25.45 19.65,26.95 18.9,27.7 16.9,27.7 16.7,27.5 16.7,26.7 17.8,25.6
SE_GND on TOP: 42.12,12.2 41.22,13.1 41.22,18.7 42.6,20.08 42.6,33.4 41.7,34.3 41.3,34.3 40.8,33.8 40.8,33.2 41.7,32.3 41.7,26.1 40.5,24.9 40.5,24 41.2,23.3 41.2,19.7 40.4,18.9 40.4,12.3 41.7,11 43,11 44,10 44,6.22 45.1,5.12 45.1,4.8 46.3,3.6 47.7,3.6 48.8,2.5 50.4,2.5 50.8,2.9 50.8,5.5 49.2,7.1 49.2,8.8 51.2,10.8 51.2,11.4 50.6,12 48.8,12 48.8,13.9 48.5,14.2 48.3,14.2 48.1,14 47.6,14 46.9,14.7 45.4,14.7 45.4,12.8 44.8,12.2
SE_GND on TOP: 46.22,18.45 46.22,15.88 47.4,14.7 49.62,14.7 49.82,14.9 49.82,16 48.42,17.4 48.02,17.4 47.62,17.8 47.62,18.4 47.57,18.45
SE_GND on BOTTOM: 54.27,1.17 54.27,12.33 53.9,12.7 50.67,12.7 49.97,12 49.97,10.7 50.29,10.39 53.41,10.39 53.8,10 53.8,8 53.6,7.8 53.6,2.3 53.5,2.2 51.2,2.2 50.8,2.6 50.8,3.5 50.5,3.8 49.6,3.8 49.2,3.4 46.9,3.4 46.9,0.3 53.4,0.3
SE_GND on BOTTOM: 47.82,7.6 47.82,9.2 47.62,9.4 45.42,9.4 45.02,9.8 44.02,9.8 43.92,9.7 43.92,8 45.12,8 45.22,7.9 45.22,7.5 45.32,7.4 47.62,7.4
SE_GND on BOTTOM: 42.74,19.04 42.2,18.5 41.3,18.5 41.1,18.7 41.1,19.5 41.6,20 41.6,22.2 42.5,23.1 43.6,23.1 43.6,22.54 43.4,22.34 42.9,22.34 42.74,22.19
TYPE-C_GND on TOP: 42.02,12.8 41.52,13.3 41.52,18.5 43.1,20.08 43.1,34.4 44.1,35.4 51.22,35.4 51.22,34.1 51.12,34 47.62,34 47.12,33.5 47.12,32.8 48.14,31.78 48.8,31.78 48.95,31.63 48.95,31.42 48.84,31.3 47.83,31.3 47.82,31.3 47.02,31.3 46.62,31.7 46.32,31.7 46.31,31.69 45.69,31.69 45.2,31.2 45.2,23.3 45.9,22.6 45.9,20.1 45.3,19.5 44.22,19.5 43.12,18.4 43.12,15.48 43.92,14.68 43.92,13.12 43.6,12.8
TYPE-C_GND on BOTTOM: 47.43,23.9 48.4,24.87 48.4,25.4 48.3,25.5 46.2,25.5 45.9,25.8 45.9,32 45.6,32.3 44.9,32.3 44.6,32 44.6,25.7 44.4,25.5 44.4,24.2 44.7,23.9
TYPE-C_GND on BOTTOM: 48.42,34 51.12,34 51.22,34.1 51.22,34.9 51.02,35.1 48.42,35.1 48.22,34.9 48.22,34.2
N14611440 on BOTTOM (solid shape): 10.85,12.4 10.85,10.6 9.55,10.6 9.45,10.7 9.45,12.4 10.15,13.1
N14642330 on BOTTOM (solid shape): 10.85,16.3 10.85,14.6 10.15,13.9 9.45,14.6 9.45,16.4 10.75,16.4
N14642346 on BOTTOM (solid shape): 3.35,16.3 3.35,14.6 2.65,13.9 1.95,14.6 1.95,16.4 3.25,16.4
N14649078 on BOTTOM (solid shape): 43.58,7.46 41.87,7.46 41.87,9.74 43.58,9.74
N14649078 on TOP: 43.7,8 43.7,9.5 42.7,10.5 39.4,10.5 38.7,9.8 38.7,8.3 39.3,7.7 43.4,7.7
N14649078 on BOTTOM: 38.8,10 39.4,10.6 43.12,10.6 43.22,10.5 43.22,10 43.42,9.8 43.62,9.8 43.62,7.1 43.92,6.8 43.92,3.9 43.62,3.6 41,3.6 40.5,4.1 40.5,5.3 41.1,5.9 41.1,7.2 40.3,8 39.3,8 38.8,8.5
N14702573 on TOP: 53.2,19.7 53.2,15.1 53.4,14.9 54.1,14.9 54.37,15.17 54.37,19.63 54.1,19.9 53.4,19.9
N14702669 on BOTTOM (solid shape): 50.98,14.85 50.98,14.64 51.39,14.23 51.91,14.23 51.95,14.19 51.95,13.6 51.92,13.57 51.2,13.57 50.18,14.59 50.18,14.9 50.93,14.9
N14702673 on BOTTOM (solid shape): 51.93,15.26 51.93,14.61 51.43,14.61 51.23,14.82 51.23,14.96 51.06,15.12 50.16,15.12 50.15,15.13 50.15,15.4 50.16,15.41 51.79,15.41
N14785189 on BOTTOM (solid shape): 29.1,13.9 29.2,13.8 31.3,13.8 31.5,13.6 31.5,12.5 31.8,12.2 31.8,11.5 31.6,11.3 30.5,11.3 30.4,11.4 29.4,11.4 29.3,11.5 26.3,11.5 26.1,11.7 26.1,13.1 27.4,14.4 29.1,14.4
N14862769 on TOP (solid shape): 22.29,27.21 22.29,26.37 22.27,26.35 21.86,26.35 21.76,26.24 21.76,25.9 21.61,25.75 21.4,25.75 21.24,25.9 21.24,26.11 20.89,26.45 20.5,26.45 20.47,26.48 20.47,27.12 20.5,27.15 21.53,27.15 21.63,27.25 22.24,27.25
N158920421 on BOTTOM: 49.2,6.3 44.7,6.3 44.6,6.2 44.6,4.1 44.8,3.9 49,3.9 49.5,4.4 49.5,6

Small or netless copper shapes (teardrops, artwork), in the pictures only: 5 on TOP, 8 on BOTTOM

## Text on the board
BOTTOM: 600-XXXXX-XX REV01 SECONDARY SIDE
Ref Des/Assembly Bottom: SECONDARY SIDE | PAG1S+PAG1P 18W SOLUTION | ASSEMBLY DRAWING | BOARD | 620-XXXXX-XX
Board Geometry/Soldermask Bottom: 600-XXXXX-XX REV01 SECONDARY SOLDER MASK
Ref Des/Silkscreen Bottom: PAG1S+PAG1P 20W | CY-SD1125 REV01 | SOLUTION DEMO KIT | A | 600-XXXXX-XX REV01 SECONDARY SILKSCREEN
User.Comments: 22/09/20 | PVV | HUSA | GGAN
TOP: 600-XXXXX-XX REV01 PRIMARY SIDE
Ref Des/Assembly Top: ASSEMBLE WIRES FROM L_ TO L(ACC9) | ASSEMBLE WIRES FROM N_ TO N THROUGH RT2 (ACC10) | INSERT PCB BLADE FROM TOP SIDE | ASSEMBLE ACC11 ON PCB BEFORE INSTALLING T1(TRANSFORMER) | CUT T1 HERE | SOLDER THE FLYING LEAD FROM T1 TO THIS POINT | (CLEAR) | (BLACK) | FL4 | FL5 | RT2 | PRIMARY SIDE
Board Geometry/Soldermask Top: 600-XXXXX-XX REV01 SOLDER MASK PRIMARY SIDE
Ref Des/Silkscreen Top: 1 | 7 | A | K | 2 | 3 | VBUS | FL5 | FL4 | 600-XXXXX-XX REV01 PRIMARY SILKSCREEN
DIMENSION: +/-0.1 | 48 mils | 1.2 mm | +/-10% | LAYER 2 BOTTOM,2 OZ | LAYER 1 TOP,2 OZ | CORE | PRIMARY SIDE | SECONDARY SIDE | X4 | X3 | 0.5mm Slot | 1.2mm Slot | X2 | A. FR4 OR EQUIVALENT MATERIAL(HIGH ELECTRONIC RELIABILITY) MUST CONFIRM TO UL94V-0 | 1. RoHS COMPLIANT CERTIFICATION OR MATERIAL DECLARATION REQUIRED. | 2. MATERIAL: | B. USE HTE COPPER, AS SPECIFIED IN THE CROSS SECTION DIAGRAM. | 3. DRILLING: | A. DIAMETERS IN DRILL TABLE ARE FINISHED HOLE SIZES +/-.003 tol. | UNLESS OTHERWISE SPECIFIED IN DRILL TABLE. | B. TEARDROP ALLOWED ON ENTRY OF VIA ON EVERY TRACE LAYER. | 4. PLATING: | COPPER PLATING IN THRU-HOLES .001 min. | 5. MARKING: | A. SILKSCREEN IN WHITE NON-CONDUCTIVE EPOXY INK ON PRIMARY SIDE OF THE | BOARD OR BOTH SIDES IF APPLICABLE. | B. FABRICATOR TO PLACE DATE CODE, LOGO AND RoHS COMPILANT SYMBOL IN SILKSCREEN ON SECONDARY SIDE. | 6. FINAL FABRICATION: | A. SOLDRMASK PRIMARY AND SECONDARY SIDE OF BOARD USING LIQUID PHOTOIMAGABLE | MASK MATERIAL OVER BARE COPPER. PER IPC-SM-840. MASK ARTWORKS PROVIDED | ARE 1:1. SOLDERMASK COLOR *BLUE** | 7. FINISH: | A. SHALL BE ELECTROLESS NIKEL / IMMERSION GOLD(ENIG). | B. NICKEL THICKNESS: 100-200 MICROINCHES. | C. GOLD THICKNESS: 3-10 MICROINCHES. | 8. BOARDS SHALL BE PURCHASED FROM UL RECOGNIZED VENDORS ONLY. | FLAMABILITY RATING (94-V0). | 9. MANUFACTURE BOARD TO BE IN ACCORDANCE WITH PERFORMANCE STANDARD | IPC-6011/6012 CLASS 2 BOARD TO BE INSPECTED PER IPC-600-A CLASS 2. | 10.MAXIMUM WRAP OR TWIST SHALL NOT EXCEED .007 in/in. | 12.ENSURE ALL THE VIA HOLES ARE FILLED WITH SOLDER MASK TO ENSURE GOOD QUALITY OF SILK SCREEN PRINT. | 13.CARE MUST BE TAKEN TO AVOID OVER ETCHING OF COPPER ON PADS. | 14.THIS IS HIGH VOLTAGE BOARD.SO DON'T ADD THIEVING COPPER IN VOID AREA FOR COPPER BALANCE. | 11.TESTING: | A. FABRICATOR TO ADD TEST STRUCTURES OR CUPONS AS NEEDED. | B. T-LINE IMPEDENCE TO BE TESTED OR GUARANTEE WITHIN 10% IF SPECIFIED IN | 15.MANUFACTURE BOARD TO BE IN ACCORDANCE WITH CTI STANDARD OF 400>CTI<600 | C. OVERALL METAL TO METAL THICKNESS AS SPECIFIED IN THE CROSS SECTION. | THE CROSS SECTION.  TOLERANCE TO BE +/-10% UNLESS OTHERWISE SPECIFIED. | NOTES:(UNLESS OTHERWISE SPECIFIED)
PAGE_OUTLINE: REV | 198 CHAMPION COURT | SAN JOSE, CA 95134 | (408) 943-2600 | 22/09/20 | INITIAL RELEASE | 1 | GGAN | DEMO BOARD | PAG1S+PAG1P 20W SOLUTION | C | 01
User.15: 1 | 7 | 2 | MOSFET Q1 | 3 | PCB | MOSFET HAS TO INSERTED COMPLETELY & | SOLDERED FROM BOTTOM SIDE OF THE PCB | 600-XXXXX-XX REV01 PRIMARY ASSEMBLY
User.23: 600-XXXXX-XX REV01 SECONDARY ASSEMBLY
User.41: 600-XXXXX-XX REV01 PRIMARY SOLDERPASTE
User.42: 600-XXXXX-XX REV01 SECONDARY SOLDERPASTE
User.45: FIGURE | SIZE | 0.254 | 0.508 | 0.7 | 0.75 | 0.85 | 0.904 | 0.92 | 1.0 | 1.4 | 1.5 | 0.65 | 1.4x0.5999 | 1.4x0.9 | 1.7x0.5999 | 6.731x1.905 | DRILL CHART: TOP to BOTTOM | ALL UNITS ARE IN MILLIMETERS | TOLERANCE | +0.0762/-0.0762 | +0.0508/-0.0508 | PLATED | NON-PLATED | QTY | 64 | 5 | 4 | 9 | 2 | 10 | 1 | 3 | DO NOT DISCLOSE TO OR DUPLICATE FOR | PROPRIETARY INFORMATION THAT IS | CYPRESS SEMICONDUCTOR PROPERTY. | OTHERS EXCEPT AS AUTHIRIZED BY CYPRESS. | THIS DOUCUMENT CONTAINS CONFIDENTAL, | REV | DWG NO | FSCM NO | SCALE: | SHEET: | DATE | SIGNATURES | ENGRG : | ISSUED | DRAWN : | CHECKED : | ANGLES +/- 2 | UNLESS OTHERWISE SPECIFIED | PROJECTIONS | DIMENSIONS ARE IN INCHES | TOLERANCES ON; | 2 PL DECIMALS +/- .010 | 3 PL DECIMALS +/- .005 | THIRD ANGLE | 06/02/17 | 27/08/19 | 2 OF 2 | FAB | PRVE | HUSAIN | HITS | SEMICONDUCTOR | REVISIONS | CYPRESS PROPRIETARY | APPROVED | 26/06/19 | DESCRIPTION | PVV | HUSA | RAJA | 198 CHAMPION COURT | SAN JOSE, CA 95134 | (408) 943-2600 | 1/1 | ALPHA RELEASE | INITIAL RELEASE | FABRICATION DRAWING | ASSEMBLY DRAWING | CYPRESS | 620-XXXXX-XX | 610-XXXXX-XX | 02 | C
